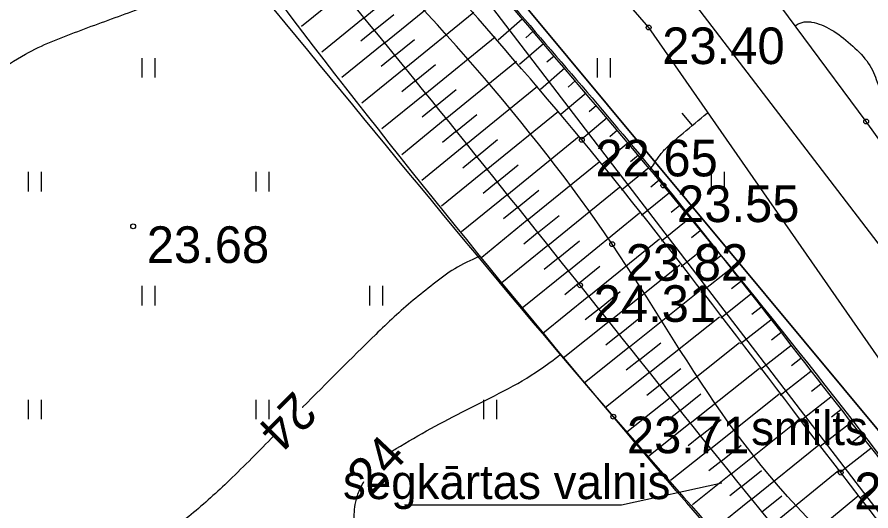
# Model space of a CAD drawing. Extents: x 521824 to 524158, y 294774 to 296228.
# Drawn here: x 522122.65 to 522148.91, y 295838.18 to 295853.36 of the extents above; entities that cross this region are included whole.
import ezdxf

# ---------------------------------------------------------------- set-up
doc = ezdxf.new("R2010")
doc.units = 0
for name, color, linetype in [('7315030100', 7, 'Continuous'), ('CELI_CMAL_####_####_#', 7, 'Continuous'), ('GL4 Segkartas izplatības laukums', 7, 'Continuous'), ('GL7 Citi Izplatības laukumi', 7, 'Continuous'), ('RELJ_AATZ_####_TKST_#', 7, 'Continuous'), ('RELJ_ELEM_####_####_#', 7, 'Continuous'), ('RELJ_HORZ_####_TKST_#', 7, 'Continuous'), ('RELJ_HORZ_PAMT_####_#', 7, 'Continuous'), ('RELJ_HORZ_RESN_####_#', 7, 'Continuous'), ('RELJ_NOGA_####_####_#', 7, 'Continuous'), ('RELJ_NOGL_####_####_#', 7, 'Continuous'), ('TERT_ELEM_####_####_#', 7, 'Continuous'), ('TERT_IZMT_####_TKST_#', 7, 'Continuous'), ('TERT_KONT_####_####_#', 7, 'Continuous')]:
    doc.layers.add(name, color=color, linetype=linetype)

msp = doc.modelspace()

# ---------------------------------------------------------------- linework, layer by layer
at = {"layer": '7315030100'}
msp.add_lwpolyline([(521982.6621484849, 296071.9435568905), (522030.78400000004, 296022.73900000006), (522033.5410000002, 296023.5089999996), (522041.3830000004, 296002.9110000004), (522075.3820000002, 295945.0490000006), (522118.8880000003, 295885.8499999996), (522163.66299999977, 295827.4399999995), (522159.46399999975, 295824.69800000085), (522114.8890000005, 295882.8479999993), (522071.2010000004, 295942.2949999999), (522036.86299999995, 296000.73299999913), (522028.99600000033, 296021.0460000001), (521979.24799999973, 296071.9199999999), (521979.2263936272, 296071.94480188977)], dxfattribs=at)
at = {"layer": 'CELI_CMAL_####_####_#'}
for points in [[(522172.092, 295817.657), (522166.319, 295825.15), (522160.036, 295834.4430000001), (522148.759, 295850.151), (522144.922, 295855.32800000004), (522137.14400000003, 295864.043), (522128.853, 295872.455), (522121.32200000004, 295880.759), (522112.36500000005, 295890.512), (522105.478, 295899.02900000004), (522098.35400000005, 295909.472), (522089.453644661, 295921.09464466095), (522081.842, 295931.152), (522074.717, 295941.169), (522065.954, 295953.62700000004)], [(522095.856, 295905.56700000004), (522095.856, 295905.56700000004), (522102.541, 295897.227), (522109.814, 295887.993), (522118.24600000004, 295878.42600000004), (522126.721, 295869.938), (522134.59400000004, 295861.6280000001), (522142.07200000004, 295853.04000000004), (522149.466, 295842.40400000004), (522156.738, 295832.411), (522163.775, 295823.088), (522169.38300000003, 295816.077)]]:
    msp.add_lwpolyline(points, dxfattribs=at)
at = {"layer": 'GL4 Segkartas izplatības laukums'}
msp.add_lwpolyline([(522069.63, 295797.668), (522066.6245064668, 295799.3774776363), (522066.821, 295800.191), (522078.81700000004, 295806.63300000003), (522081.268320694, 295807.8271870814), (522087.6908621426, 295812.09928898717), (522093.4905087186, 295816.2776405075), (522098.79571581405, 295820.26733720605), (522107.34300000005, 295832.723), (522111.787, 295855.21900000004), (522106.5222183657, 295875.48821839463), (522108.8492994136, 295877.62784059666), (522114.174, 295882.652), (522149.292, 295840.47000000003), (522151.58, 295837.93200000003), (522131.531, 295829.31200000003), (522119.09400000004, 295822.70800000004), (522104.069, 295811.941), (522092.118, 295802.865), (522086.39400000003, 295802.68), (522071.7450000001, 295796.673)], close=True, dxfattribs=at)
at = {"layer": 'GL7 Citi Izplatības laukumi'}
msp.add_lwpolyline([(522151.58, 295837.93200000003), (522149.292, 295840.47000000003), (522114.174, 295882.652), (522108.8492994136, 295877.62784059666), (522106.5222183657, 295875.48821839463), (522111.787, 295855.21900000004), (522107.34300000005, 295832.723), (522098.79571581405, 295820.26733720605), (522093.4905087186, 295816.2776405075), (522087.6908621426, 295812.09928898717), (522081.268320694, 295807.8271870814), (522078.81700000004, 295806.63300000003), (522066.821, 295800.191), (522066.6245064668, 295799.3774776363), (522069.63, 295797.668), (522071.7450000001, 295796.673), (522086.39400000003, 295802.68), (522092.118, 295802.865), (522104.069, 295811.941), (522119.09400000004, 295822.70800000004), (522131.531, 295829.31200000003)], dxfattribs=at)
at = {"layer": 'RELJ_ELEM_####_####_#'}
for centre in [(522142.07200000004, 295853.04000000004), (522148.759, 295850.151), (522140.016, 295849.58900000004), (522142.526, 295848.184), (522126.222, 295846.929), (522140.951, 295846.381), (522139.96300000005, 295845.118), (522140.98600000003, 295841.081), (522147.977, 295839.362)]:
    msp.add_circle(centre, 0.075, dxfattribs=at)
at = {"layer": 'RELJ_HORZ_PAMT_####_#'}
msp.add_line((522143.0909487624, 295850.40888297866), (522143.4110937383, 295850.0248163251), dxfattribs=at)
for points in [[(522105.81441437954, 295830.5828906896), (522105.7978445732, 295831.67310712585), (522105.6947603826, 295832.19370203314), (522105.57024194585, 295832.4318142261), (522105.48357907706, 295832.54331689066), (522105.3783006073, 295832.6490193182), (522105.02831824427, 295832.7881442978), (522104.6513761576, 295832.7030008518), (522104.2650133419, 295832.5235873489), (522103.8867687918, 295832.3799021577), (522103.63796493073, 295832.29123918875), (522103.3875089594, 295832.17731161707), (522103.02311065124, 295832.0967811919), (522102.9079416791, 295832.1255155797), (522102.72449514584, 295832.2784257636), (522102.5708200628, 295832.47811749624), (522102.32301553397, 295832.7707875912), (522101.87821765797, 295833.3342501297), (522102.3100474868, 295834.18793752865), (522102.77009610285, 295834.6019915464), (522104.96819830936, 295837.0824560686), (522105.7592106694, 295838.17734928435), (522106.72604443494, 295839.2730473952), (522107.3030135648, 295839.6658262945), (522107.97956875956, 295839.92050180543), (522108.65731316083, 295840.2003575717), (522108.9658822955, 295840.40075418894), (522109.23784991, 295840.6686772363), (522110.0190165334, 295842.0959102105), (522110.3146551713, 295843.62960655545), (522110.30937722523, 295844.02927229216), (522110.25887470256, 295844.4298455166), (522110.2055292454, 295844.8304353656), (522110.41924999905, 295845.64565947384), (522111.08370288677, 295846.95323414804), (522112.27249894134, 295848.86100962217), (522113.94741143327, 295850.1292034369), (522114.4367184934, 295850.67032081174), (522117.26318941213, 295849.46826610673), (522118.1640792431, 295849.5243103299), (522118.6139739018, 295849.5817520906), (522119.0633822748, 295849.665634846), (522120.1203108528, 295850.11170266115), (522121.05320409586, 295850.81533406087), (522121.9530556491, 295851.58319752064), (522122.9108591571, 295852.22196151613), (522124.51943663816, 295852.9208849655), (522126.18500280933, 295853.53250522), (522127.84635405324, 295854.17420976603), (522129.442286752, 295854.9633860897), (522129.7118496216, 295855.13249653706)], [(522146.576461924, 295853.0957484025), (522146.5764619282, 295853.09574840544), (522146.69775956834, 295853.16329074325), (522146.8262120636, 295853.20303598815), (522146.95633403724, 295853.21654107), (522147.08264011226, 295853.2053629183), (522147.38662802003, 295853.11871330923), (522147.6820829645, 295852.9713848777), (522148.27902005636, 295852.5280905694), (522148.77768095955, 295852.0097562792), (522148.95083036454, 295851.7316271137), (522149.06996416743, 295851.43776109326), (522149.18345684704, 295851.1448243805), (522149.33968288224, 295850.86948313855), (522149.61705139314, 295850.59789043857), (522149.69772556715, 295850.57328171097), (522149.77893267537, 295850.5544231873), (522149.94272394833, 295850.52504123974), (522150.26940348, 295850.47148762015), (522150.92529322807, 295850.41517027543), (522151.2549262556, 295850.40931911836), (522151.5849892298, 295850.4130686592), (522152.2437637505, 295850.45601726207), (522152.7392684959, 295850.51188784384), (522153.23403210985, 295850.57152802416), (522153.7285930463, 295850.63143016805), (522154.2234897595, 295850.68808664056), (522154.88001519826, 295850.75421472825), (522155.080483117, 295850.79110230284), (522155.2775007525, 295850.8471739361), (522155.47329517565, 295850.90882042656), (522155.670093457, 295850.9624325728), (522156.06048865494, 295851.0365902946), (522156.25787276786, 295851.0401016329), (522156.3552617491, 295851.02631688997), (522156.45107736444, 295850.99944862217), (522156.77056329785, 295850.77297377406), (522156.8330364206, 295850.69270858), (522156.88757810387, 295850.6098795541), (522156.9734581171, 295850.4335449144), (522157.0173121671, 295850.31808146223)], [(522142.12387165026, 295848.6747642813), (522142.1987751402, 295848.7928410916), (522142.27566743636, 295848.9095894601), (522142.3548795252, 295849.0249097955), (522142.4367423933, 295849.1387025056), (522142.51307748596, 295849.2310852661), (522142.5961071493, 295849.3176324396), (522142.76877195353, 295849.48278156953), (522143.1329852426, 295849.79270397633), (522143.87332886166, 295850.4088856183), (522143.8909729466, 295850.42347359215)]]:
    msp.add_spline(points, degree=3, dxfattribs=at)
at = {"layer": 'RELJ_HORZ_RESN_####_#'}
for points in [[(522136.8627401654, 295845.99898173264), (522136.1077623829, 295845.6261024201), (522135.44998280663, 295845.15166861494), (522134.8332777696, 295844.65993117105), (522133.67970762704, 295843.6050632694), (522131.42698971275, 295841.3685036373), (522131.4230042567, 295841.3645362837)], [(522134.1498955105, 295839.99831799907), (522134.31142975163, 295840.09828573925), (522136.4668040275, 295841.2889152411), (522138.7291470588, 295842.5274933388), (522139.35296613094, 295842.98570600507)], [(522130.5504650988, 295840.4928024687), (522129.18010716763, 295839.1241503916), (522128.00575338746, 295838.07145793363), (522127.3910606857, 295837.57395153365), (522126.7695585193, 295837.07973039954), (522126.5613309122, 295836.9473654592), (522126.0472382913, 295836.74030552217), (522125.5240131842, 295836.5852511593), (522124.45403408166, 295836.43286909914), (522122.2458567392, 295836.3472270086), (522120.04016552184, 295836.2753011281), (522118.9753899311, 295836.1265310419), (522118.4533879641, 295835.98262618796), (522117.9403270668, 295835.8019533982), (522116.42434096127, 295835.1707961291), (522114.9406397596, 295834.48852372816), (522114.342936, 295834.1868241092), (522114.04473175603, 295834.0344123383), (522113.74186935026, 295833.8895688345), (522112.9695249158, 295833.63047035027), (522112.1608072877, 295833.48158824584), (522111.34009855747, 295833.3517083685), (522110.5317808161, 295833.1496165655), (522110.0270850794, 295832.99062893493), (522109.53205849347, 295832.808773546), (522109.04455118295, 295832.6040665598), (522108.56241327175, 295832.3765241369), (522108.1212717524, 295832.11280915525), (522107.7183549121, 295831.7907274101), (522107.37440040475, 295831.4139231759), (522107.0988455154, 295830.96819379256), (522107.06674773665, 295830.749932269), (522107.07682112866, 295830.52597772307), (522107.1720723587, 295830.08364778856)], [(522146.84215387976, 295834.67841970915), (522146.7270998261, 295834.5985684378), (522146.5722487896, 295834.4368239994), (522146.4982765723, 295834.26282595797), (522146.46237834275, 295834.08155042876), (522146.46084674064, 295833.992466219), (522146.4662139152, 295833.90270631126), (522146.5036877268, 295833.7261602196), (522146.9456512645, 295832.5100271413), (522147.3833850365, 295831.3914658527), (522147.42714487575, 295831.2003308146), (522147.422067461, 295831.10187367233), (522147.39141407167, 295831.0066798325), (522147.2899155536, 295830.8798942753), (522147.14728363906, 295830.81177300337), (522146.7368156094, 295830.7862994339), (522146.3166883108, 295830.8156763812), (522145.4637129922, 295831.00896068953), (522144.62087185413, 295831.33158365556), (522143.82067906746, 295831.7235030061), (522143.5461331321, 295831.9053246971), (522143.290561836, 295832.1150744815), (522143.0284495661, 295832.3137411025), (522142.7342807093, 295832.462313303), (522142.091274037, 295832.6581974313), (522141.44336916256, 295832.8005433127), (522141.1165309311, 295832.85234445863), (522140.7893094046, 295832.8927268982), (522140.1335421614, 295832.91817651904), (522139.40071662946, 295832.883414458), (522139.0343121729, 295832.8607883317), (522138.66799603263, 295832.85430344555), (522137.7733156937, 295832.8836480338), (522137.32644305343, 295832.91824708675), (522136.87969847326, 295832.9641880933), (522136.43448009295, 295833.0447317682), (522136.21435679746, 295833.09961822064), (522135.9946561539, 295833.1593016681), (522135.7674357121, 295833.22829139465), (522135.5451629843, 295833.3085910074), (522135.32712212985, 295833.40114922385), (522135.1125973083, 295833.5069147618), (522134.7913525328, 295833.703830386), (522134.49790337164, 295833.9386733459), (522134.23448748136, 295834.20655658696), (522133.9954431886, 295834.50978519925), (522133.5880468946, 295835.200306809), (522133.3223997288, 295835.93982694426), (522133.0498362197, 295837.4503979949), (522133.01927484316, 295838.07270556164), (522133.0512807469, 295838.3850151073), (522133.134121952, 295838.6948563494), (522133.3168642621, 295839.0885999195)]]:
    msp.add_spline(points, degree=3, dxfattribs=at)
at = {"layer": 'RELJ_NOGA_####_####_#'}
for p, q in [((522133.2928924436, 295853.3199322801), (522135.36596189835, 295855.00864432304)), ((522132.6613172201, 295854.09524688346), (522131.3995428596, 295853.06638826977)), ((522133.9244629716, 295852.54461384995), (522136.0309894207, 295854.26057979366)), ((522133.2928924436, 295853.3199322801), (522132.02178169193, 295852.2844917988)), ((522133.6086777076, 295852.93227306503), (522134.23565318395, 295853.4430041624)), ((522134.5557507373, 295851.76906518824), (522136.6947488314, 295853.50989123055)), ((522138.1864541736, 295853.29706666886), (522137.4440674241, 295852.6543182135)), ((522133.6086777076, 295852.93227306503), (522133.2255297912, 295852.6201626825)), ((522135.1868850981, 295850.99339167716), (522137.35496728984, 295852.7567573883)), ((522138.51372941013, 295852.9190575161), (522138.2910898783, 295852.7262992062)), ((522133.9244629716, 295852.54461384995), (522132.6403949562, 295851.4986184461)), ((522134.24013891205, 295852.1568656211), (522134.8771837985, 295852.67532532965)), ((522138.8410046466, 295852.54104836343), (522138.0976909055, 295851.89749733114)), ((522134.24013891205, 295852.1568656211), (522133.85252050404, 295851.84140193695)), ((522135.8178653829, 295850.2175928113), (522138.00957870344, 295852.0001784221)), ((522139.1682798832, 295852.16303921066), (522138.9444585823, 295851.96925774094)), ((522134.5557507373, 295851.76906518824), (522133.25553760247, 295850.71088524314)), ((522134.8713625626, 295851.3812647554), (522135.51745217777, 295851.9070855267)), ((522139.4950538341, 295851.7845972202), (522138.74329646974, 295851.1372369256)), ((522134.8713625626, 295851.3812647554), (522134.4786724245, 295851.0616734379)), ((522136.44875437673, 295849.44171971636), (522138.6584518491, 295851.2379415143)), ((522139.8210704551, 295851.4055023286), (522139.5936220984, 295851.21044392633)), ((522135.1868850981, 295850.99339167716), (522133.8686180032, 295849.92120585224)), ((522135.50237524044, 295850.60549224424), (522136.1565488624, 295851.1375511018)), ((522140.1465140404, 295851.02591516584), (522139.3805411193, 295850.37152648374)), ((522140.47105271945, 295850.6455541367), (522140.2385615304, 295850.4475248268)), ((522135.50237524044, 295850.60549224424), (522135.10412463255, 295850.2815831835)), ((522136.1333555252, 295849.8296933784), (522136.79375563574, 295850.3668164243)), ((522137.0795252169, 295848.66575054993), (522139.2992737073, 295850.47014263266)), ((522135.8178653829, 295850.2175928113), (522134.48094839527, 295849.1302384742)), ((522140.79473877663, 295850.2644673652), (522140.0079228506, 295849.59905376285)), ((522141.1173246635, 295849.8824489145), (522140.87776249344, 295849.6807035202)), ((522136.1333555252, 295849.8296933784), (522135.72944099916, 295849.5011776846)), ((522136.76413979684, 295849.0537351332), (522137.42886198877, 295849.5940753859)), ((522137.71029605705, 295847.88978138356), (522139.93092748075, 295849.6948911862)), ((522136.44875437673, 295849.44171971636), (522135.0928938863, 295848.3395660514)), ((522141.43884683, 295849.4995348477), (522140.62843549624, 295848.82025308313)), ((522136.76413979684, 295849.0537351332), (522136.3546342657, 295848.7208557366)), ((522141.7590879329, 295849.1155488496), (522141.5118541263, 295848.9105845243)), ((522137.394910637, 295848.2777659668), (522138.0613379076, 295848.8194922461)), ((522138.341002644, 295847.11375999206), (522140.5547873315, 295848.91295073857)), ((522137.0795252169, 295848.66575054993), (522135.70573331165, 295847.5490207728)), ((522142.0778641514, 295848.730346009), (522141.24212322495, 295848.0418977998)), ((522137.394910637, 295848.2777659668), (522136.98028590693, 295847.9407252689)), ((522142.39517510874, 295848.3439355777), (522142.1411317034, 295848.1361319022)), ((522138.0256545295, 295847.5017748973), (522138.6909996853, 295848.04251531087)), ((522138.971698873, 295846.3377301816), (522141.174537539, 295848.12802485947)), ((522137.71029605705, 295847.88978138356), (522136.3204651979, 295846.76001384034)), ((522142.71102893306, 295847.95633300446), (522141.85396078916, 295847.2597787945)), ((522138.0256545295, 295847.5017748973), (522137.6065259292, 295847.1611400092)), ((522143.0258670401, 295847.5679046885), (522142.7659018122, 295847.35772966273)), ((522138.6563507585, 295846.7257450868), (522139.3189951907, 295847.2642905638)), ((522139.60239510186, 295845.56170037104), (522141.7910433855, 295847.340462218)), ((522138.341002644, 295847.11375999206), (522136.9377150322, 295845.97327776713)), ((522143.33987857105, 295847.1788076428), (522142.46444901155, 295846.4739449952)), ((522138.6563507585, 295846.7257450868), (522138.2337608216, 295846.38229709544)), ((522143.6529573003, 295846.78895952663), (522143.3878393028, 295846.57626342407)), ((522139.2870469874, 295845.9497152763), (522139.94589679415, 295846.48517677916)), ((522140.23271145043, 295844.7853621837), (522142.4068502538, 295846.548210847)), ((522138.971698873, 295846.3377301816), (522137.55889033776, 295845.1895100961)), ((522143.9651941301, 295846.3984368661), (522143.0729980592, 295845.6858447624)), ((522139.2870469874, 295845.9497152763), (522138.8622916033, 295845.60450737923)), ((522144.27688391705, 295846.0074774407), (522144.0068712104, 295845.79261846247)), ((522139.9177432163, 295845.17368546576), (522140.57189701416, 295845.7053304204)), ((522140.86041018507, 295844.00690680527), (522143.0272686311, 295845.7452279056)), ((522139.60239510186, 295845.56170037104), (522138.1847448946, 295844.40954535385)), ((522144.58782579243, 295845.6159227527), (522143.6810277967, 295844.89627186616)), ((522139.9177432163, 295845.17368546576), (522139.4923312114, 295844.82794391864)), ((522144.89814658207, 295845.2238755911), (522144.62424771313, 295845.00711658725)), ((522140.5469110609, 295844.3964169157), (522141.19786304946, 295844.9218373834)), ((522141.48546968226, 295843.2263300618), (522143.64010140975, 295844.9494178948)), ((522140.23271145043, 295844.7853621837), (522138.8149488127, 295843.6358031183)), ((522145.20788347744, 295844.83136693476), (522144.2892264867, 295844.10647957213)), ((522140.5469110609, 295844.3964169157), (522140.1220157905, 295844.0534597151)), ((522145.51710600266, 295844.43845297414), (522145.239959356, 295844.2204084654)), ((522141.1731904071, 295843.6168190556), (522141.8217287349, 295844.13546383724)), ((522142.1086944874, 295842.44428751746), (522144.25509418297, 295844.1508029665)), ((522140.86041018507, 295844.00690680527), (522139.4471135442, 295842.8731163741)), ((522145.82591245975, 295844.0452120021), (522144.8973642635, 295843.3167663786)), ((522141.1731904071, 295843.6168190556), (522140.75140603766, 295843.2795124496)), ((522146.1343280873, 295843.65166456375), (522145.8542854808, 295843.43296424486)), ((522141.7971750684, 295842.83538286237), (522142.44238151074, 295843.3496977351)), ((522142.73102030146, 295841.66152920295), (522144.86564897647, 295843.357951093)), ((522141.48546968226, 295843.2263300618), (522140.0912061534, 295842.1113188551)), ((522146.44207760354, 295843.2575957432), (522145.50592503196, 295842.52650389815)), ((522141.7971750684, 295842.83538286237), (522141.38268103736, 295842.5049762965)), ((522146.7498271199, 295842.8635269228), (522146.4683341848, 295842.64369396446)), ((522142.41986156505, 295842.0529116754), (522143.0619619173, 295842.5634196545)), ((522143.3531893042, 295840.87864624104), (522145.47585077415, 295842.5655576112)), ((522142.1086944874, 295842.44428751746), (522140.74252373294, 295841.3581004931)), ((522147.057576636, 295842.4694581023), (522146.1176366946, 295841.7354084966)), ((522142.41986156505, 295842.0529116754), (522142.0159100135, 295841.73174616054)), ((522147.36532615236, 295842.0753892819), (522147.0829888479, 295841.8548969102)), ((522143.04210480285, 295841.270087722), (522143.6806983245, 295841.777587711)), ((522143.9758880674, 295840.096184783), (522146.08558174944, 295841.77673602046)), ((522142.73102030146, 295841.66152920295), (522141.405406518, 295840.60804375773)), ((522147.6730756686, 295841.68132046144), (522146.731420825, 295840.9459315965)), ((522143.04210480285, 295841.270087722), (522142.6510749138, 295840.95933031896)), ((522147.98082518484, 295841.287251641), (522147.6983434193, 295841.0666464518)), ((522143.66435548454, 295840.4872697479), (522144.2988980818, 295840.9927371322)), ((522144.5999725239, 295839.3148284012), (522146.69535385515, 295840.9922432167)), ((522143.3531893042, 295840.87864624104), (522142.07295631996, 295839.8612256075)), ((522148.28857470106, 295840.8931828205), (522147.3478851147, 295840.1585477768)), ((522143.66435548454, 295840.4872697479), (522143.2878905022, 295840.1873832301)), ((522148.5963242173, 295840.4991140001), (522148.3146298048, 295840.2791236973)), ((522144.2876700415, 295839.70529873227), (522144.9183807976, 295840.20899341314)), ((522145.22637268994, 295838.5353276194), (522147.3061127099, 295840.21166714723)), ((522143.9758880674, 295840.096184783), (522142.7455353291, 295839.1161037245)), ((522148.90407373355, 295840.1050451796), (522147.9676794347, 295839.3737645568)), ((522144.2876700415, 295839.70529873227), (522143.9264928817, 295839.416857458)), ((522144.9128382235, 295838.9248092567), (522145.5391691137, 295839.42773506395)), ((522145.8556795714, 295837.75817198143), (522147.91863484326, 295839.43566937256)), ((522144.5999725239, 295839.3148284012), (522143.42257700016, 295838.372288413)), ((522149.51957276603, 295839.31690753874), (522148.5894675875, 295838.5905384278)), ((522144.9128382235, 295838.9248092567), (522144.5677052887, 295838.64767737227)), ((522145.540672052, 295838.1464631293), (522146.1619830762, 295838.6496157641)), ((522146.48885867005, 295836.98416833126), (522148.53218110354, 295838.66269623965)), ((522145.22637268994, 295838.5353276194), (522144.10317175, 295837.62999035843))]:
    msp.add_line(p, q, dxfattribs=at)
for points in [[(522157.9073553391, 295825.4033553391), (522159.06600000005, 295826.51800000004), (522156.80645671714, 295830.2750716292), (522151.05064466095, 295837.373355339), (522142.526, 295848.184), (522133.612, 295858.662), (522124.39, 295869.90400000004), (522117.34943299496, 295878.46614491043), (522115.10500000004, 295880.075), (522113.824, 295878.38800000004)], [(522156.272, 295825.614), (522148.59400000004, 295834.485), (522139.96300000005, 295845.118), (522131.29600000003, 295855.769), (522123.482, 295864.8780000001), (522113.51, 295876.949)]]:
    msp.add_spline(points, degree=3, dxfattribs=at)
at = {"layer": 'RELJ_NOGL_####_####_#'}
for points in [[(522157.77300000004, 295827.023), (522157.87200000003, 295825.368), (522156.8138430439, 295824.483601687), (522155.071, 295825.376), (522154.4157255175, 295826.43018908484), (522151.8136290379, 295829.3257378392), (522140.98600000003, 295841.081), (522130.14800000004, 295854.6060000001), (522118.868, 295867.895), (522112.737, 295876.058), (522113.2986392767, 295878.0255479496), (522113.824, 295878.38800000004), (522115.39200000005, 295878.049)], [(522157.77300000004, 295827.023), (522147.977, 295839.362), (522140.016, 295849.58900000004), (522131.454, 295859.47500000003), (522123.498, 295869.164), (522115.39200000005, 295878.049)]]:
    msp.add_spline(points, degree=3, dxfattribs=at)
at = {"layer": 'TERT_ELEM_####_####_#'}
for p, q in [((522126.5, 295851.5), (522126.5, 295852.10000000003)), ((522126.9, 295851.5), (522126.9, 295852.10000000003)), ((522140.5, 295851.5), (522140.5, 295852.10000000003)), ((522140.9, 295851.5), (522140.9, 295852.10000000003)), ((522123, 295848), (522123, 295848.60000000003)), ((522123.4, 295848), (522123.4, 295848.60000000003)), ((522130, 295848), (522130, 295848.60000000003)), ((522130.4, 295848), (522130.4, 295848.60000000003)), ((522144, 295848), (522144, 295848.60000000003)), ((522144.4, 295848), (522144.4, 295848.60000000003)), ((522126.5, 295844.5), (522126.5, 295845.10000000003)), ((522126.9, 295844.5), (522126.9, 295845.10000000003)), ((522133.5, 295844.5), (522133.5, 295845.10000000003)), ((522133.9, 295844.5), (522133.9, 295845.10000000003)), ((522123, 295841), (522123, 295841.60000000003)), ((522123.4, 295841), (522123.4, 295841.60000000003)), ((522130, 295841), (522130, 295841.60000000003)), ((522130.4, 295841), (522130.4, 295841.60000000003)), ((522137, 295841), (522137, 295841.60000000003)), ((522137.4, 295841), (522137.4, 295841.60000000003))]:
    msp.add_line(p, q, dxfattribs=at)
at = {"layer": 'TERT_IZMT_####_TKST_#'}
msp.add_lwpolyline([(522134.56462066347, 295838.37008186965), (522141.23479682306, 295838.37008186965), (522144.32341340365, 295839.0460286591)], dxfattribs=at)
at = {"layer": 'TERT_KONT_####_####_#'}
for points in [[(522112.737, 295876.058), (522112.737, 295877.51455323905), (522113.8446896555, 295878.3905175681), (522123.086, 295867.722), (522132.03, 295856.813), (522140.951, 295846.381), (522148.93700000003, 295836.168), (522157.87200000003, 295825.368), (522156.95989990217, 295824.47003253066), (522155.7794142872, 295824.7184870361), (522155.071, 295825.376), (522140.98600000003, 295841.081), (522129.85114007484, 295854.43447290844), (522118.868, 295867.895), (522112.737, 295876.058)], [(522113.824, 295878.38800000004), (522115.10500000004, 295880.075), (522116.5519780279, 295879.5176271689), (522128.1031053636, 295865.4696861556), (522131.4996345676, 295861.338800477), (522136.521227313, 295855.31825432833), (522141.58674069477, 295849.3855993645), (522147.8381112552, 295841.49004127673), (522154.279804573, 295833.447997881), (522158.86219095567, 295828.02804149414), (522159.4038788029, 295827.0319414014), (522158.9939528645, 295826.19697514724), (522157.9115556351, 295825.277834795)]]:
    msp.add_spline(points, degree=3, dxfattribs=at)

# ---------------------------------------------------------------- texts
at = {"layer": 'RELJ_AATZ_####_TKST_#'}
for s, p in [(' 23.40', (522142.07200000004, 295851.91500000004)), (' 22.65', (522140.016, 295848.46400000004)), (' 23.55', (522142.526, 295847.059)), (' 23.68', (522126.222, 295845.804)), (' 23.82', (522140.951, 295845.256)), (' 24.31', (522139.96300000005, 295843.993)), (' 23.71', (522140.98600000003, 295839.956)), (' 22.91', (522147.977, 295838.237))]:
    msp.add_text(s, height=1.125, dxfattribs=at).set_placement(p)
at = {"layer": 'RELJ_HORZ_####_TKST_#'}
for rotation, p in [(224.9839432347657, (522131.1723542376, 295841.9100850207)), (46.737229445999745, (522133.52382349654, 295838.60769237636))]:
    msp.add_text('24', height=1.125, rotation=rotation, dxfattribs=at).set_placement(p)
at = {"layer": 'TERT_IZMT_####_TKST_#'}
for s, p in [('smilts', (522145.2232780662, 295840.2064946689)), ('segkārtas valnis', (522132.67366945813, 295838.5470276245))]:
    msp.add_text(s, height=1.0499999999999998, dxfattribs=at).set_placement(p)

doc.saveas('drawing.dxf')
